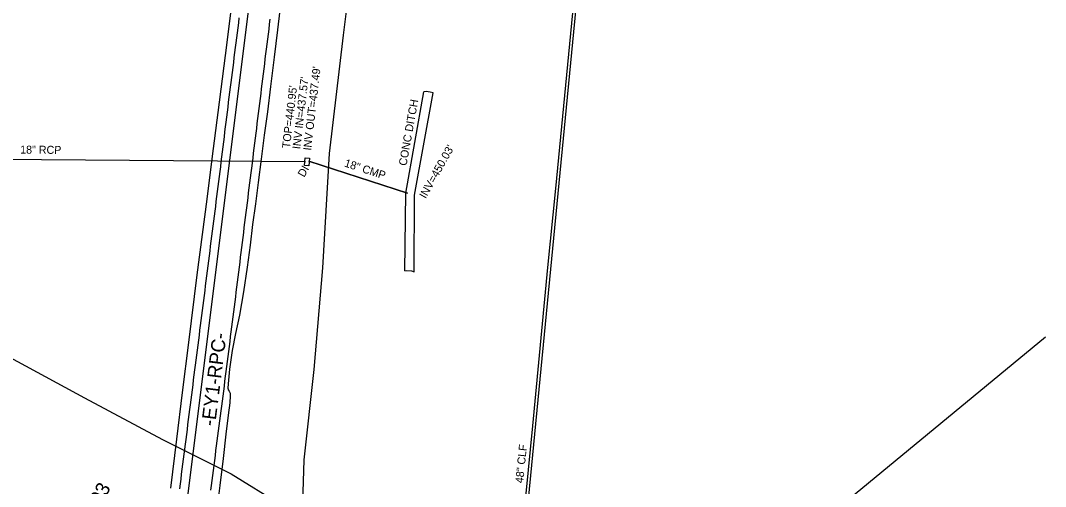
# Model space of a CAD drawing. Extents: x 2074109 to 2077820, y 741079 to 746031.
# Drawn here: x 2075866 to 2076378, y 743337 to 743570 of the extents above; entities that cross this region are included whole.
import ezdxf

# ---------------------------------------------------------------- set-up
doc = ezdxf.new("R2010")
doc.units = 0
for name, color, linetype in [('Exist Horizontal Alignment', 7, 'Continuous'), ('Exist Horizontal Alignment Direction Label', 7, 'Continuous'), ('Exist Horizontal Baseline Alignment Station Label', 7, 'Continuous'), ('Exist Other Culture Fence Line', 7, 'Continuous'), ('Exist Other Culture Fence Line Text', 7, 'Continuous'), ('Exist Property Line', 7, 'Continuous'), ('Exist Right of Way Line', 7, 'Continuous'), ('Exist Roads EOP', 7, 'Continuous'), ('Exist Roads EOT', 7, 'Continuous'), ('Exist Structure Minor Drop Inlet', 7, 'Continuous'), ('Exist Structure Minor Drop Inlet Text', 7, 'Continuous'), ('Exist Structure Minor Drop Inlet Top Elevation', 7, 'Continuous'), ('Exist Structure Minor Paved Ditch or Gutter', 7, 'Continuous'), ('Exist Structure Minor Paved Ditch or Gutter Text', 7, 'Continuous'), ('Exist Structure Minor Pipes CMP 18 Inch', 7, 'Continuous'), ('Exist Structure Minor Pipes CMP 18 Inch Invert', 7, 'Continuous'), ('Exist Structure Minor Pipes CMP 18 Inch Text', 7, 'Continuous'), ('Exist Structure Minor Pipes RCP 18 Inch', 7, 'Continuous'), ('Exist Structure Minor Pipes RCP 18 Inch Invert', 7, 'Continuous'), ('Exist Structure Minor Pipes RCP 18 Inch Text', 7, 'Continuous'), ('Exist Utilities Gas UG Line SUE LOS B', 7, 'Continuous'), ('Exist Vegetation Woods Line', 7, 'Continuous')]:
    doc.layers.add(name, color=color, linetype=linetype)

msp = doc.modelspace()

# ---------------------------------------------------------------- linework, layer by layer
at = {"layer": 'Exist Horizontal Alignment'}
msp.add_line((2075929.78, 743173.21), (2075997.63, 743717.85), dxfattribs=at)
msp.add_arc((2065746.77, 748969.72), 11283.45, 330.581241, 339.398504, dxfattribs=at)
at = {"layer": 'Exist Other Culture Fence Line'}
msp.add_lwpolyline([(2076099.74, 743133.39), (2076108.49, 743228.73), (2076114.14, 743288.02), (2076122.13, 743367.47), (2076129.58, 743446.69), (2076133.48, 743486.09), (2076144.08, 743594.72), (2076153.23, 743687.73), (2076160.69, 743765.12), (2076167.44, 743833.03), (2076174.97, 743912.27), (2076182.21, 743989.53), (2076189.98, 744071.72), (2076191.42, 744084.49), (2076221.56, 744153.97), (2076252.09, 744225.13), (2076285, 744306.14), (2076323.53, 744397.86)], dxfattribs=at)
at = {"layer": 'Exist Property Line'}
msp.add_line((2076378.34, 743411.87), (2076105.92, 743187.4), dxfattribs=at)
at = {"layer": 'Exist Right of Way Line'}
msp.add_line((2076192.48, 744084.19), (2076105.92, 743187.4), dxfattribs=at)
at = {"layer": 'Exist Roads EOP'}
for points in [[(2075941.09, 743336.36), (2075944.11, 743360.86), (2075946.95, 743384.21), (2075950.08, 743409.16), (2075954.27, 743442.89), (2075956.84, 743463.1), (2075959.19, 743480.85), (2075961.8, 743500.96), (2075965.41, 743529.22), (2075969.19, 743559.12), (2075973.45, 743592.79)], [(2075995.51, 743575.25), (2075994.35, 743565.35), (2075992.71, 743551.69), (2075990.94, 743537.13), (2075989.34, 743524.51), (2075987.81, 743512.74), (2075986.26, 743500.72), (2075984.74, 743489.07), (2075983.33, 743478.42), (2075981.98, 743468.19), (2075980.69, 743457.79), (2075979.23, 743446.72), (2075977.4, 743434.47), (2075975.41, 743422.83), (2075973.45, 743413.6), (2075971.73, 743405.16), (2075970.42, 743395.87), (2075969.7, 743388.42), (2075969.63, 743386.38), (2075969.67, 743385.78), (2075969.75, 743385.47), (2075970.19, 743384.77), (2075970.62, 743384.08), (2075970.71, 743383.85), (2075970.77, 743383.5), (2075970.81, 743382.44), (2075970.53, 743378.92), (2075969.8, 743372.77), (2075968.66, 743363.25), (2075967.2, 743351.23), (2075965.54, 743337.59), (2075963.87, 743324.42)]]:
    msp.add_lwpolyline(points, dxfattribs=at)
at = {"layer": 'Exist Roads EOT'}
for points in [[(2075945.54, 743335.95), (2075945.85, 743338.43), (2075946.17, 743340.9), (2075946.49, 743343.38), (2075946.8, 743345.86), (2075947.12, 743348.34), (2075947.43, 743350.81), (2075947.75, 743353.29), (2075948.07, 743355.77), (2075948.38, 743358.25), (2075948.7, 743360.73), (2075949.02, 743363.2), (2075949.34, 743365.68), (2075949.66, 743368.16), (2075949.98, 743370.64), (2075950.3, 743373.12), (2075950.61, 743375.59), (2075950.93, 743378.07), (2075951.25, 743380.55), (2075951.56, 743383.03), (2075951.88, 743385.51), (2075952.19, 743387.98), (2075952.5, 743390.46), (2075952.82, 743392.94), (2075953.13, 743395.42), (2075953.44, 743397.9), (2075953.76, 743400.38), (2075954.07, 743402.86), (2075954.39, 743405.33), (2075954.71, 743407.81), (2075955.02, 743410.29), (2075955.34, 743412.77), (2075955.65, 743415.25), (2075955.97, 743417.72), (2075956.29, 743420.2), (2075956.6, 743422.68), (2075956.92, 743425.16), (2075957.23, 743427.64), (2075957.55, 743430.11), (2075957.86, 743432.59), (2075958.17, 743435.07), (2075958.49, 743437.55), (2075958.8, 743440.03), (2075959.12, 743442.51), (2075959.43, 743444.98), (2075959.74, 743447.46), (2075960.06, 743449.94), (2075960.37, 743452.42), (2075960.69, 743454.9), (2075961, 743457.38), (2075961.32, 743459.85), (2075961.63, 743462.33), (2075961.95, 743464.81), (2075962.26, 743467.29), (2075962.58, 743469.77), (2075962.89, 743472.25), (2075963.2, 743474.73), (2075963.52, 743477.2), (2075963.83, 743479.68), (2075964.14, 743482.16), (2075964.46, 743484.64), (2075964.77, 743487.12), (2075965.08, 743489.6), (2075965.39, 743492.08), (2075965.71, 743494.55), (2075966.02, 743497.03), (2075966.32, 743499.51), (2075966.63, 743501.99), (2075966.93, 743504.47), (2075967.24, 743506.95), (2075967.54, 743509.43), (2075967.85, 743511.91), (2075968.15, 743514.39), (2075968.46, 743516.87), (2075968.76, 743519.35), (2075969.07, 743521.83), (2075969.37, 743524.31), (2075969.67, 743526.79), (2075969.98, 743529.26), (2075970.3, 743531.74), (2075970.61, 743534.22), (2075970.93, 743536.7), (2075971.25, 743539.18), (2075971.56, 743541.66), (2075971.88, 743544.13), (2075972.19, 743546.61), (2075972.51, 743549.09), (2075972.82, 743551.57), (2075973.14, 743554.05), (2075973.45, 743556.52), (2075973.77, 743559), (2075974.08, 743561.48), (2075974.4, 743563.96), (2075974.71, 743566.44), (2075975.01, 743568.92), (2075975.32, 743571.4)], [(2075990.63, 743570.73), (2075990.32, 743568.25), (2075990.01, 743565.77), (2075989.7, 743563.29), (2075989.39, 743560.81), (2075989.08, 743558.33), (2075988.78, 743555.85), (2075988.47, 743553.38), (2075988.16, 743550.9), (2075987.85, 743548.42), (2075987.54, 743545.94), (2075987.24, 743543.46), (2075986.93, 743540.98), (2075986.62, 743538.5), (2075986.31, 743536.02), (2075986.01, 743533.54), (2075985.7, 743531.06), (2075985.39, 743528.58), (2075985.08, 743526.1), (2075984.78, 743523.63), (2075984.47, 743521.15), (2075984.16, 743518.67), (2075983.85, 743516.19), (2075983.55, 743513.71), (2075983.24, 743511.23), (2075982.93, 743508.75), (2075982.62, 743506.27), (2075982.31, 743503.79), (2075982, 743501.31), (2075981.69, 743498.84), (2075981.38, 743496.36), (2075981.07, 743493.88), (2075980.75, 743491.4), (2075980.44, 743488.92), (2075980.13, 743486.44), (2075979.82, 743483.96), (2075979.51, 743481.48), (2075979.2, 743479.01), (2075978.89, 743476.53), (2075978.58, 743474.05), (2075978.27, 743471.57), (2075977.96, 743469.09), (2075977.66, 743466.61), (2075977.35, 743464.13), (2075977.04, 743461.65), (2075976.73, 743459.17), (2075976.42, 743456.69), (2075976.12, 743454.21), (2075975.81, 743451.74), (2075975.5, 743449.26), (2075975.19, 743446.78), (2075974.88, 743444.3), (2075974.57, 743441.82), (2075974.27, 743439.34), (2075973.96, 743436.86), (2075973.65, 743434.38), (2075973.34, 743431.9), (2075973.03, 743429.42), (2075972.71, 743426.95), (2075972.4, 743424.47), (2075972.08, 743421.99), (2075971.77, 743419.51), (2075971.45, 743417.03), (2075971.14, 743414.56), (2075970.82, 743412.08), (2075970.51, 743409.6), (2075970.19, 743407.12), (2075969.88, 743404.64), (2075969.57, 743402.16), (2075969.25, 743399.69), (2075968.94, 743397.21), (2075968.62, 743394.73), (2075968.31, 743392.25), (2075967.99, 743389.77), (2075967.68, 743387.3), (2075967.36, 743384.82), (2075967.05, 743382.34), (2075966.73, 743379.86), (2075966.4, 743377.38), (2075966.08, 743374.91), (2075965.76, 743372.43), (2075965.43, 743369.95), (2075965.11, 743367.48), (2075964.79, 743365), (2075964.46, 743362.52), (2075964.14, 743360.05), (2075963.82, 743357.57), (2075963.49, 743355.09), (2075963.17, 743352.62), (2075962.85, 743350.14), (2075962.52, 743347.66), (2075962.2, 743345.18), (2075961.88, 743342.71), (2075961.55, 743340.23), (2075961.23, 743337.75), (2075960.91, 743335.28)]]:
    msp.add_lwpolyline(points, dxfattribs=at)
at = {"layer": 'Exist Structure Minor Drop Inlet'}
msp.add_lwpolyline([(2076007.92, 743497.56), (2076008.22, 743501.38), (2076010.38, 743501.21), (2076010.08, 743497.39)], close=True, dxfattribs=at)
at = {"layer": 'Exist Structure Minor Paved Ditch or Gutter'}
for points in [[(2076058.04, 743444.98), (2076059.01, 743445.08), (2076061.39, 743445.01), (2076062.77, 743444.42), (2076062.92, 743482.79), (2076072.18, 743533.9), (2076070.75, 743534.25), (2076068.71, 743534.59), (2076067.62, 743534.41)], [(2076058.06, 743445.04), (2076058.49, 743483.73), (2076067.6, 743534.4)]]:
    msp.add_lwpolyline(points, dxfattribs=at)
at = {"layer": 'Exist Structure Minor Pipes CMP 18 Inch'}
for p, q in [((2076010.02, 743499.84), (2076059.32, 743483.78)), ((2076059.32, 743483.78), (2076010.02, 743499.84))]:
    msp.add_line(p, q, dxfattribs=at)
at = {"layer": 'Exist Structure Minor Pipes RCP 18 Inch'}
msp.add_line((2075747.2, 743501.45), (2076008.33, 743499.7), dxfattribs=at)
at = {"layer": 'Exist Utilities Gas UG Line SUE LOS B'}
msp.add_lwpolyline([(2075544.69, 743574.93), (2075774.64, 743449.58), (2075786.68, 743440.92), (2075834.72, 743415.6), (2075897.9, 743381.57), (2075936.93, 743360.69), (2075971.28, 743343.48), (2075996.08, 743328.1)], dxfattribs=at)
at = {"layer": 'Exist Vegetation Woods Line'}
msp.add_lwpolyline([(2076117.94, 743141.67), (2076108.77, 743154.74), (2076094.18, 743164.1), (2076077.81, 743169.85), (2076045.23, 743196.57), (2076024.01, 743219.19), (2076005.99, 743248.57), (2076005.83, 743291.28), (2076007.68, 743350.51), (2076012.74, 743395.68), (2076017.02, 743446.43), (2076020.44, 743503.7), (2076027.4, 743562.78), (2076033.1, 743608.23), (2076041.63, 743662.31), (2076044.09, 743714.21), (2076053.98, 743772.87), (2076068.02, 743864.63), (2076080.88, 743932.35), (2076088.49, 743961.79)], dxfattribs=at)

# ---------------------------------------------------------------- texts
at = {"layer": 'Exist Horizontal Alignment Direction Label'}
msp.add_text('-EY1-RPC-', height=7, rotation=82.859, dxfattribs=at).set_placement((2075963.19, 743367.1))
at = {"layer": 'Exist Horizontal Baseline Alignment Station Label'}
msp.add_text('BY1-1003', height=7, rotation=60.742, dxfattribs=at).set_placement((2075890.91, 743300.24))
at = {"layer": 'Exist Other Culture Fence Line Text'}
msp.add_text('48" CLF', height=4, rotation=84.2533, dxfattribs=at).set_placement((2076117.22, 743338.67))
at = {"layer": 'Exist Structure Minor Drop Inlet Text'}
msp.add_text('DI', height=4, rotation=60.7411, dxfattribs=at).set_placement((2076007.75, 743491.44))
at = {"layer": 'Exist Structure Minor Drop Inlet Top Elevation'}
msp.add_text("TOP=440.95'", height=4, rotation=83.4132, dxfattribs=at).set_placement((2076000.63, 743506.06))
at = {"layer": 'Exist Structure Minor Paved Ditch or Gutter Text'}
msp.add_text('CONC DITCH', height=4, rotation=79.8099, dxfattribs=at).set_placement((2076058.89, 743497.26))
at = {"layer": 'Exist Structure Minor Pipes CMP 18 Inch Invert'}
for s, rotation, p in [("INV IN=437.57'", 83.4132, (2076005.8, 743505.62)), ("INV=450.03'", 60.742, (2076068.5, 743480.77))]:
    msp.add_text(s, height=4, rotation=rotation, dxfattribs=at).set_placement(p)
at = {"layer": 'Exist Structure Minor Pipes CMP 18 Inch Text'}
msp.add_text('18" CMP', height=4, rotation=341.9554, dxfattribs=at).set_placement((2076027.52, 743497.19))
at = {"layer": 'Exist Structure Minor Pipes RCP 18 Inch Invert'}
msp.add_text("INV OUT=437.49'", height=4, rotation=83.4132, dxfattribs=at).set_placement((2076011.18, 743504.96))
at = {"layer": 'Exist Structure Minor Pipes RCP 18 Inch Text'}
msp.add_text('18" RCP', height=4, rotation=359.616, dxfattribs=at).set_placement((2075865.75, 743503.55))

doc.saveas('drawing.dxf')
